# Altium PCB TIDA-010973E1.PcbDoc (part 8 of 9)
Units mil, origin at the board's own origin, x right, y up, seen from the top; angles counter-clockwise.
Board outline 5166 x 3669 mil, 8 copper layers (L01 - TOP, L02 - GND, L03 - SIG, L04 - GND, L05 - PWR, L06 - SIG, L07 - GND, L08 - BOTTOM), stack 61.7 mil thick; 677 components, 493 nets, 2522 pads, 1424 vias.
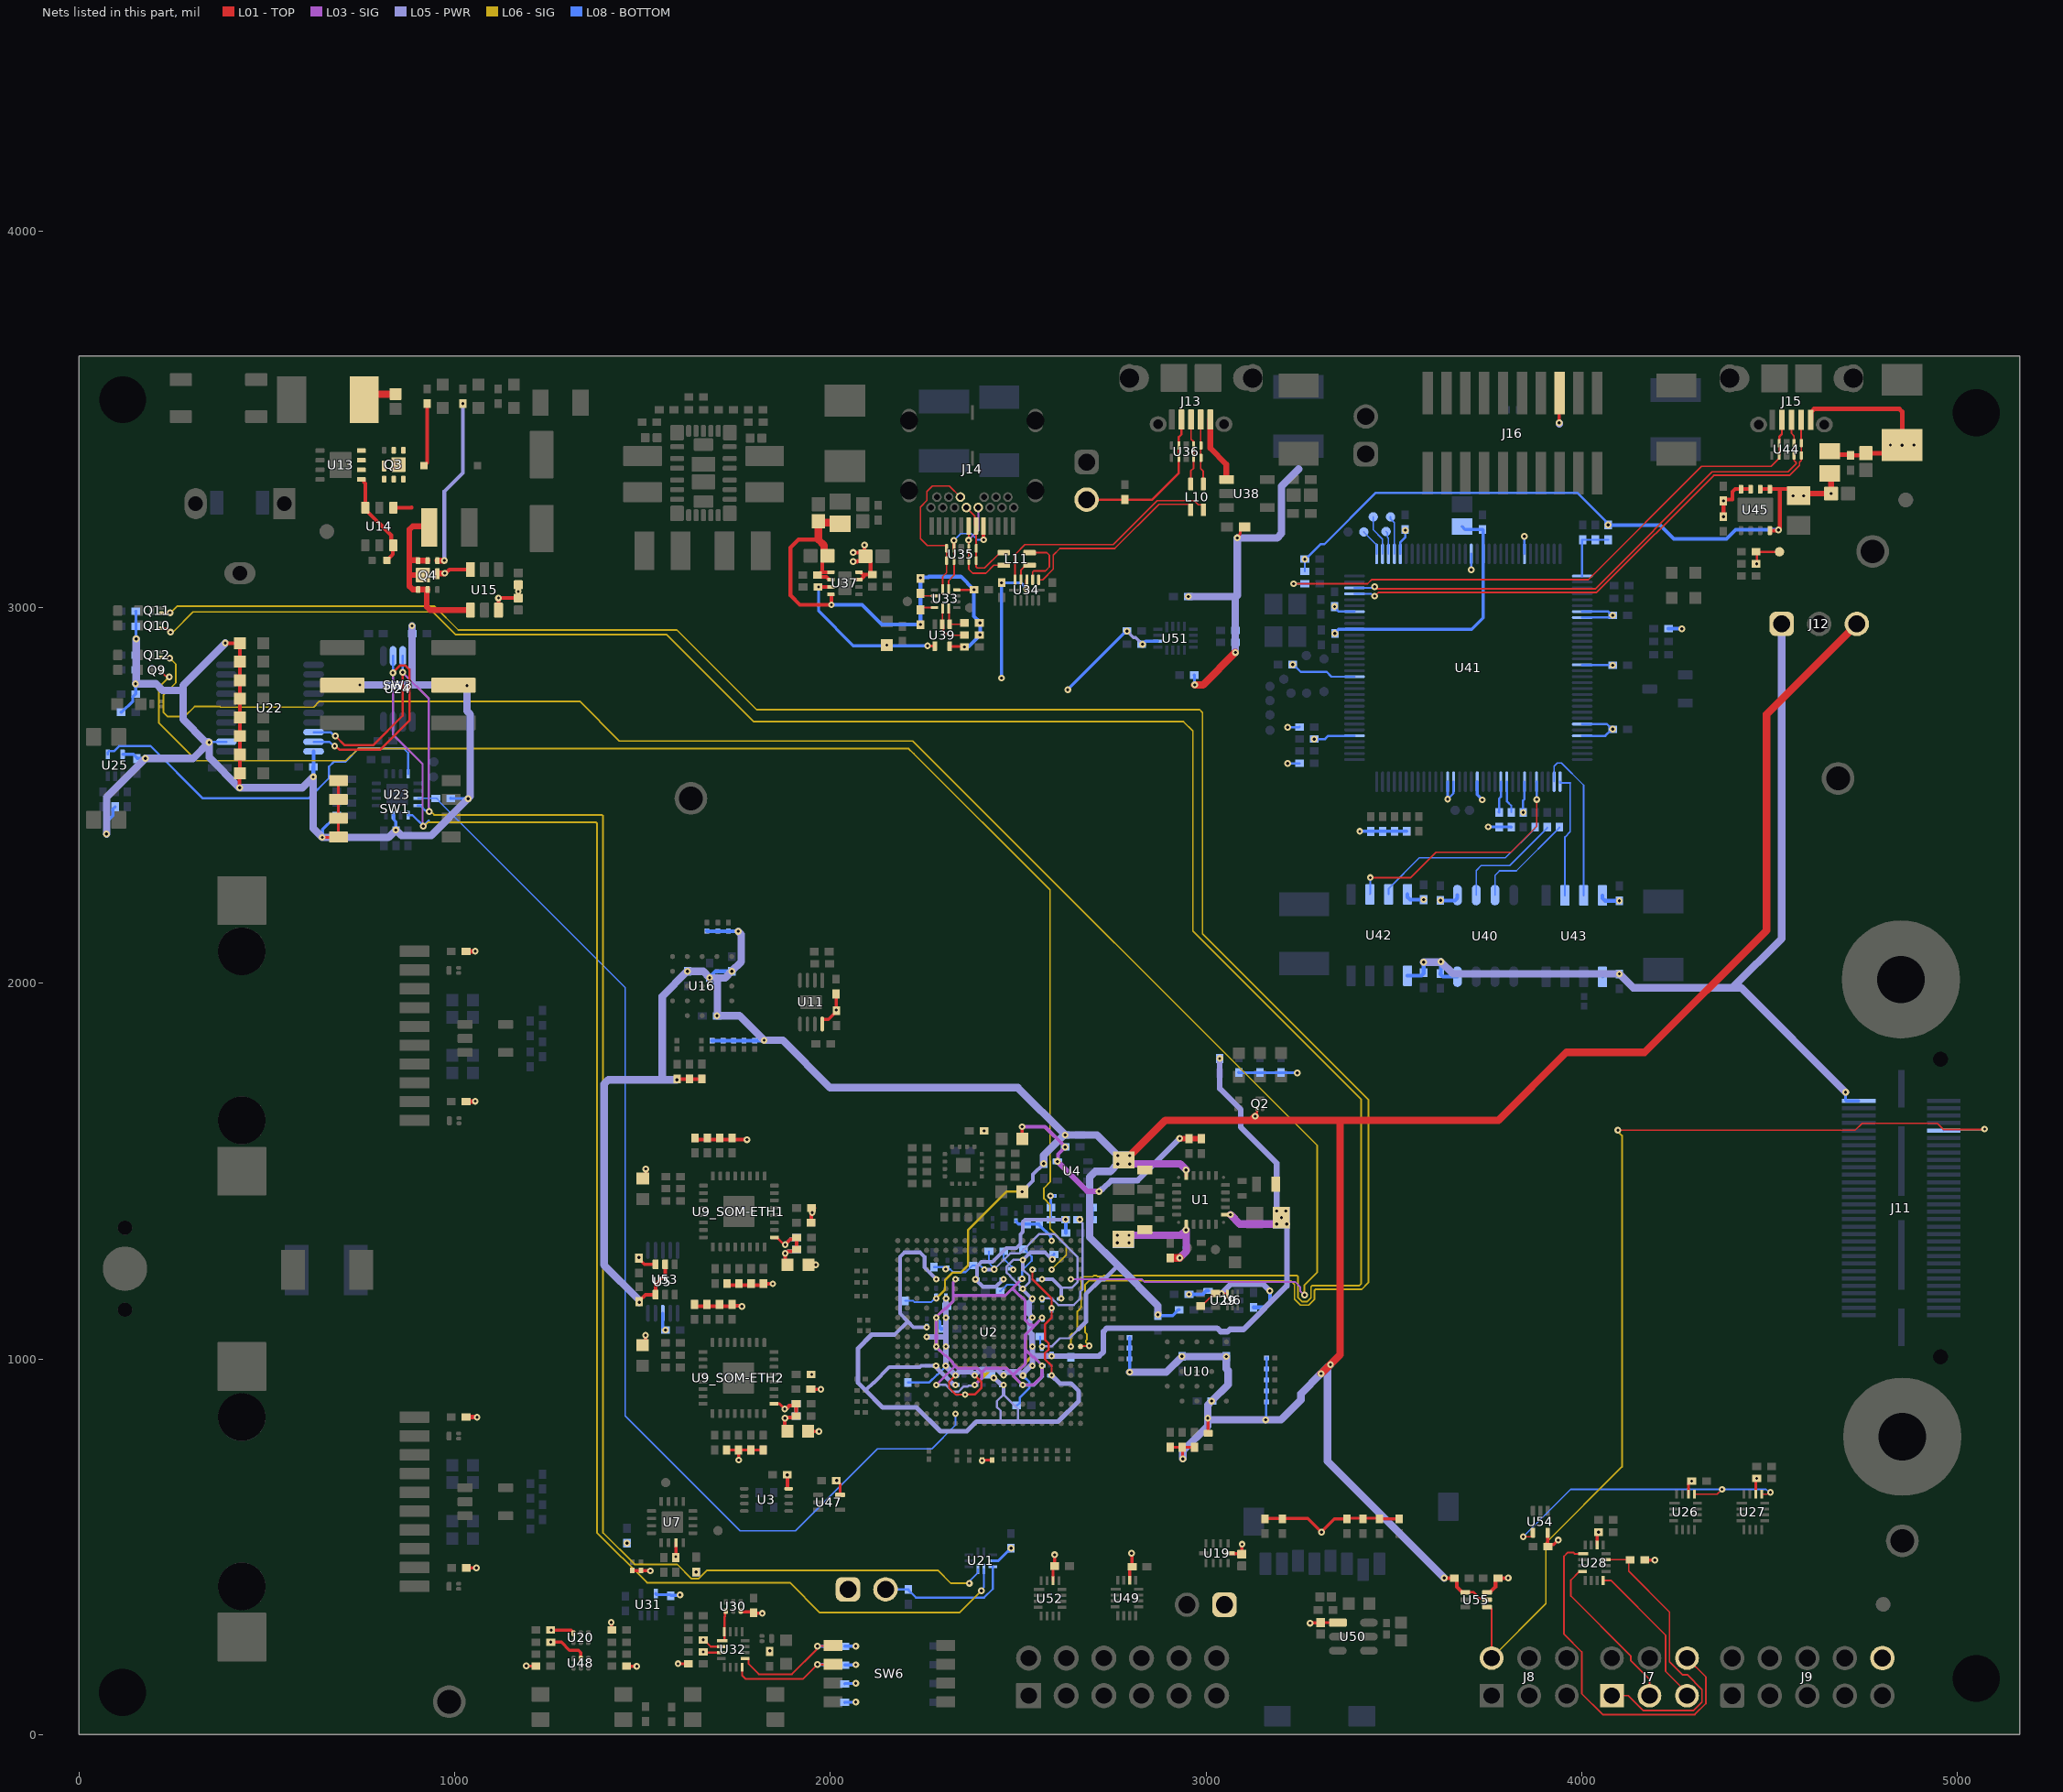
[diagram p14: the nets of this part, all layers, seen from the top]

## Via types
v1: diameter 18, hole 8, L01 - TOP to L08 - BOTTOM, tented both sides, 1389 vias
v2: diameter 19.68, hole 7.87, L01 - TOP to L08 - BOTTOM, 24 vias
v3: diameter 19.68, hole 7.87, L01 - TOP to L08 - BOTTOM, tented both sides, 11 vias

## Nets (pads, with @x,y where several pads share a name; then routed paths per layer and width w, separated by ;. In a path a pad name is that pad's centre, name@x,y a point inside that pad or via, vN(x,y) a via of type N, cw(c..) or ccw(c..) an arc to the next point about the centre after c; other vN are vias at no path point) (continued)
SOP2_SW: R125.1 SW6.6 U32.8 | length 317.1
  L01 - TOP w5: U32.8@1765.49,179.41 1765.49,157.51 1774,149 1928,149 v1(1966,187) 2006.79,187 SW6.6@2007.36,187.57
  L08 - BOTTOM w8: v1(1966,187) 1997.43,187 R125.1@1999.09,185.33
SOP3_SW: R124.1 SW6.5 U32.9 | length 328.6
  L01 - TOP w5: U32.9@1773.36,203.03 1781.24,203.03 1782.67,201.59 1782.67,188.26 1809.93,161 1898.01,161 1963.51,226.5 1963.51,233.51 v1(1966,236) 2005.79,236 SW6.5@2007.36,237.57
  L08 - BOTTOM w8: v1(1966,236) 1998.09,236 R124.1@1999.09,235
SOP_DRIVER_OEN: U30.4 U32.1 U32.16 | length 91.9
  L01 - TOP w6: U32.1@1712.34,250.28 1717.31,250.28 1718.24,251.21 U32.16@1718.24,273.9 1718.24,313.23 1719.86,314.85 U30.4@1719.86,324.85 ; U30.4@1718.24,323.23 U30.4@1719.86,324.85 ; U30.4@1722.18,327.17 U30.4@1719.86,324.85 ; U30.4@1722.18,329.65 1719.86,327.34 U30.4@1719.86,324.85
SOP_DRIVER_OEN_HPI: U26.13 U27.13 U54.4 | length 853.5
  L01 - TOP w4.3: U27.13@4478.62,640.24 4493.54,640.24 4498.29,645 v1(4502,645)
  L01 - TOP w4.5: v1@3844,528.48 v1(3844,527) 3866.37,527 3870.03,530.66 U54.4@3870.03,537.62 ; U26.13@4299.62,640.24 4360.24,640.24 v1(4373,653)
  L08 - BOTTOM w4.5: v1(3844,527) 3970,653 v1(4373,653) 4490.35,653 4498.35,645 v1(4502,645)
SPI2_CLK: J7.3 U28.4 | length 434.4
  L01 - TOP w4.5: U28.4@4001.5,434.38 3993.63,434.38 3970.75,411.5 3970.75,369.46 4130,210.21 4130,197.79 4180,147.79 J7.3@4180,104
SPI2_CS0: J7.1 R220.1 U28.11 | length 796.8
  L01 - TOP w4.5: U28.11@4064.5,465.87 4127.44,465.87 R220.1@4128.31,465 4125,461.68 4125,435 4233.5,326.5 4233.5,194.29 4267.9,159.89 4280.32,159.89 4319.75,120.46 4319.75,87.54 4296.46,64.25 4163.54,64.25 4123.79,104 J7.1@4080,104
SPI2_D0: J7.5 U28.8 | length 411.4
  L01 - TOP w4.5: U28.8@4056.62,410.76 4077.24,410.76 4223,265 4223,169 4280,112 J7.5@4280,104
SPI2_D1: J7.6 U28.1 | length 948.9
  L01 - TOP w4.5: U28.1@4003.47,481.62 3980.77,481.62 3977.15,485.25 3962.85,485.25 3952.75,475.15 3952.75,267.46 3999.75,220.46 3999.75,109.59 4055.59,53.75 4300.81,53.75 4330.25,83.19 4330.25,153.75 J7.6@4280,204
SYNC_OUT1_3V3: J8.2 J11.52 U55.4 | length 2799.8
  L01 - TOP w4.3: U55.4@3748.02,339.63 3755.31,339.63 3760,334.94 J8.2@3760,204 ; 4727.5,1608.75 4745.9,1627.15 4946.17,1627.15 4962.4,1610.92 5070.92,1610.92 v1(5072,1612)
  L01 - TOP w4.5: v1(4096,1609) 4096.25,1608.75 4727.5,1608.75
  L06 - SIG w4.5: J8.2@3760,204 3904.48,348.48 3904.48,510.48 4107,713 4107,1594.61 4096,1605.61 v1(4096,1609)
  L08 - BOTTOM w4.3: J11.52@4962.8,1608.17 4964.71,1610.09 5070.09,1610.09 v1(5072,1612)
TCK_XDS: R223.1 U40.3 | length 277.7
  L08 - BOTTOM w4.3: U40.3@3769,2234.5 3769,2287 3781,2299 3825.84,2299 3940,2413.16 R223.1@3940,2415.13
TDI_XDS: R225.1 U42.7 | length 474.4
  L08 - BOTTOM w4.3: U42.7@3486,2236.44 3486,2252.19 3567.47,2333.66 3796.5,2333.66 3876,2413.16 R225.1@3876,2415.13
TDO_XDS: U41.37 U42.6 | length 663.7
  L01 - TOP w4.3: v1(3437,2281) 3544.75,2281 3612.14,2348.39 3811.23,2348.39 3880,2417.16 v1(3880,2489)
  L08 - BOTTOM w4.3: U42.6@3436,2236.44 3437,2237.44 v1(3437,2281)
  L08 - BOTTOM w6: U41.37@3879.11,2536.15 3879.47,2535.79 3879.47,2489.53 v1(3880,2489)
TM4C129_TCK: TP10.1 U41.100 | length 102.8
  L08 - BOTTOM w4.3: TP10.1@3491,3241 3491,3235.4 3501.16,3225.24 U41.100@3501.16,3142.45
TM4C129_TDI: TP12.1 U41.98 | length 108.8
  L08 - BOTTOM w4.3: TP12.1@3445,3241 3445,3206.8 3469.66,3182.13 U41.98@3469.66,3142.45
TM4C129_TDO: TP13.1 U41.97 | length 72.6
  L08 - BOTTOM w4.3: TP13.1@3420,3201 3420,3200.49 3453.92,3166.58 U41.97@3453.92,3142.45
TM4C129_TMS: TP11.1 U41.99 | length 62.2
  L08 - BOTTOM w4.3: TP11.1@3479,3202 3482.96,3198.04 3482.96,3187.04 3485.41,3184.59 U41.99@3485.41,3142.45
TMS_XDS: R224.1 U40.2 | length 303.3
  L08 - BOTTOM w4.3: U40.2@3719,2234.5 3719,2300 3732,2313 3807.84,2313 3908,2413.16 R224.1@3908,2415.13
TPS_VSYS_5V0_ON: D19.2 R140.2 U37.3 U39.4 | length 446.8
  L01 - TOP w8: v1(2259,2898) 2259.57,2897.43 2277.75,2897.43 U39.4@2278.32,2896.87
  L01 - TOP w10: R140.2@1967.02,3054.28 v1(1968.99,3054.28) 1996.68,3054.28 1996.83,3054.44 U37.3@2001.6,3054.44
  L08 - BOTTOM w8: v1(1968.99,3054.28) 1968.99,2990.01 2061,2898 2150.28,2898 v1(2259,2898)
  other v1: 2150.28,2899.5
TUSB_OUT1: R137.1 U33.7 U39.2 | length 123.3
  L01 - TOP w4.3: U33.7@2299.13,2997.41 2298.56,2996.85 2298.56,2955.7 U39.2@2298,2955.13 2301.76,2951.38 2301.76,2936.24 2312,2926 2356.5,2926 R137.1@2357.31,2926.81
TUSB_OUT2: R136.1 U33.8 U39.1 | length 84.6
  L01 - TOP w4.3: U33.8@2314.87,2997.41 2316.28,2996 2316.28,2956.54 U39.1@2317.69,2955.13 2353.64,2955.13 R136.1@2357.31,2958.81
TUSB_OUT3: R135.1 U33.6 | length 39.8
  L01 - TOP w4.3: R135.1@2240,2993.69 2245.69,2999.38 U33.6@2277.47,2999.38
TUSB_VBUS_DET: R138.1 U33.4 | length 38.9
  L01 - TOP w4.3: R138.1@2240,3034.31 2243.44,3030.87 U33.4@2277.47,3030.87
UART0_RXD_XDS: U41.34 U43.7 | length 441.7
  L08 - BOTTOM w4.3: U41.34@3926.36,2536.15 3926.36,2577.84 3934.52,2586 3946,2586 4005,2527 U43.7@4005,2233.44
UART0_TXD_XDS: U41.33 U43.6 | length 334.9
  L08 - BOTTOM w4.5: U43.6@3955,2233.44 3955,2388.88 3969,2402.88 3969,2533
  L08 - BOTTOM w6: U41.33@3942.1,2536.15 3942.1,2533.87 3942.97,2533 3969,2533
UI_I2C_SCL: U21.2 U22.18 U23.12 U24.7 | length 4351.1
  L01 - TOP w6: v1(683,2658) 708,2633 783,2633 862,2712 v1(862,2827)
  L03 - SIG w6: v1(862,2827) 931,2758 931,2459 v1(933,2457)
  L06 - SIG w4.5: v1(933,2457) 936.65,2457 945.6,2448.05 1392.67,2448.05 1395.31,2445.42 1395.31,537.29 1479.35,453.25 1592.46,453.25 1630.65,415.07 1649.15,415.07 1671.08,437 2287,437 2321,403 v1(2370,403)
  L08 - BOTTOM w4.5: v1(2370,403) 2372.58,405.58 2372.58,410.96 2393.13,431.5 U21.2@2393.13,441.35
  L08 - BOTTOM w6: U22.18@625.08,2668.06 669.69,2668.06 679.75,2658 v1(683,2658) ; v1(862,2827) 862.06,2827.06 862.06,2870.54 U24.7@862.11,2870.6 ; U23.12@902.24,2472.63 909.32,2472.63 922.66,2459.3 930.7,2459.3 v1(933,2457)
UI_I2C_SDA: U21.1 U22.19 U23.13 U24.6 | length 4599.1
  L01 - TOP w6: v1(681,2631) 684.25,2631 694.25,2621 801.94,2621 880,2699.06 880,2834.46 869.46,2845 854.54,2845 836,2826.46 v1(836,2826)
  L03 - SIG w6: v1(836,2826) 836,2662.5 915,2583.5 915,2420 v1(917,2418)
  L06 - SIG w4.5: v1(917,2418) 919.27,2418 929.27,2428 1376.36,2428 1379,2425.36 1379,538 1512.43,404.57 1892.44,404.57 1972,325 2344,325 v1(2402,383)
  L08 - BOTTOM w4.5: v1(2402,383) 2402,386.25 2408.87,393.12 U21.1@2408.87,441.35
  L08 - BOTTOM w6: U22.19@625.08,2642.47 667.01,2642.47 678.48,2631 v1(681,2631) ; v1(836,2826) 836.26,2826.26 836.26,2870.34 U24.6@836.52,2870.6 ; U23.13@876.65,2447.04 887.96,2447.04 v1(917,2418) 932,2433
UI_I2C_SELECT: J5.2 R93.2 U21.10 | length 364.5
  L08 - BOTTOM w6: J5.2@2147,387 2207.69,387 R93.2@2208,386.69 2208,384.72 2227.72,365 2409.46,365 2432.5,388.04 U21.10@2432.5,447.25
UI_LED1_G: Q12.1 U2.T2 | length 4827.5
  L01 - TOP w4.5: Q12.1@220.01,2866.8 220.91,2865.9 241.1,2865.9 v1(242,2865)
  L03 - SIG w4.5: v1(2640.27,1212.36) 2729.83,1212.36 2828.64,1212.36 2836,1205 3237.3,1205 3250.36,1191.94 3250.36,1181.64 v1(3262,1170)
  L06 - SIG w4.5: v1(242,2865) 258.25,2848.75 258.25,2799.75 225.75,2767.25 225.75,2719.85 235.86,2709.75 281.75,2709.75 308.25,2736.25 375.74,2736.25 377.35,2734.64 625.13,2734.64 640.49,2750 1333,2750 1438.5,2644.5 2219.5,2644.5 3296,1568 3296,1231 3262,1197 v1(3262,1170)
UI_LED1_R: Q9.1 U2.U4 | length 3799.9
  L01 - TOP w4.5: Q9.1@220.01,2826.8 221.98,2826.8 231.19,2817.58 238.42,2817.58 v1(241,2815)
  L06 - SIG w4.5: v1(241,2815) 213,2787 213,2693 313.99,2592.01 711.25,2592.01 743.49,2624.25 2208.75,2624.25 2222,2611 2585,2248 2585,1527.08 2585.25,1526.83 2585.25,1471.2 2568.75,1454.7 2568.75,1426.85 2585,1410.6 2585,1346.37 2627.69,1303.68 2627.69,1276.56 v1(2589.09,1237.95)
UI_LED2_G: Q11.1 U2.J1 | length 5635.6
  L01 - TOP w4.5: U2.J1@2665.86,1033.23 2666.74,1034.11 2688.11,1034.11 v1(2689,1035)
  L01 - TOP w6: Q11.1@220.01,2984.8 241.8,2984.8 v1(243,2986)
  L06 - SIG w4.5: v1(243,2986) 244.46,2986 261.46,3003 947,3003 1010,2940 1592,2940 1804,2728 1830,2728 2983,2728 2990.5,2720.5 2990.5,2131.5 3432,1690 3432,1203.26 3414.13,1185.39 3291.29,1185.39 3288.65,1182.75 3288.65,1158.96 3273.04,1143.35 3250.96,1143.35 3235.35,1158.96 3235.35,1197.99 3225.19,1208.15 2688.42,1208.15 2678.26,1197.99 2678.26,1070.67 2683.01,1065.92 2683.01,1051.71 2679.73,1048.43 2679.73,1044.27 v1(2689,1035)
UI_LED2_R: Q10.1 U2.J2 | length 5604.1
  L01 - TOP w6: Q10.1@220.01,2944.8 232.75,2944.8 243.54,2934 v1(244,2934)
  L06 - SIG w4.5: v1(244,2934) 246.3,2936.3 252.44,2936.3 304.15,2988 942,2988 1002,2928 1564,2928 1796,2696 2940,2696 2965,2671 2965,2139 3413,1691 3413,1200.64 3407.25,1194.89 3281.79,1194.89 3279.15,1192.25 3279.15,1162.9 3269.1,1152.85 3254.9,1152.85 3244.85,1162.9 3244.85,1219.36 3242.21,1222 2727.25,1222 2725.1,1219.85 2710.9,1219.85 2708.75,1222 2701.25,1222 2698.1,1218.85 2670.49,1218.85 2667.86,1216.21 2667.86,1137.08 2657.42,1126.64 2657.42,1077.31 2647.37,1067.26 2642.9,1067.26 2640.27,1064.62 v1(2640.27,1033.23)
USB-AB_C_DM: J13.2 L10.1 U36.5 U36.6 | length 174.6
  L01 - TOP w4.5: J13.2@2985.59,3500.07 2985.59,3369.41 2992.73,3362.27 L10.1@2992.73,3328.45
USB-AB_C_DP: J13.3 L10.4 U36.4 U36.7 | length 177.7
  L01 - TOP w4.5: L10.4@2959.27,3328.45 2959.27,3363.07 2967,3370.8 U36.4@2967,3398.13 U36.7@2967,3431 2967,3440.83 2960,3447.83 J13.3@2960,3500.07
USB-AB_ID: J13.4 J20.2 R132.2 U36.2 U36.9 | length 420.1
  L01 - TOP w6: J20.2@2682,3287 2857,3287 2927.63,3357.63 U36.2@2927.63,3398.13 U36.9@2927.63,3431 2927.63,3453.58 2934.41,3460.36 J13.4@2934.41,3500.07
USB-C_D_M: J14.A7 J14.B7 L11.4 U35.2 U35.9 | length 319
  L01 - TOP w4.3: J14.A7@2368.16,3216.64 2368.42,3216.37 2368.42,3157.7 U35.2@2368.69,3157.44 U35.9@2368.69,3124.56 2368.69,3101.31 2379,3091 2414.1,3091 2435.37,3112.27 L11.4@2461.55,3112.27
  L03 - SIG w4.5: v1(2368,3179) 2393.75,3204.75 J14.B7@2393.75,3265.85
USB-C_D_P: J14.A6 J14.B6 L11.1 U35.1 U35.10 | length 260.2
  L01 - TOP w4.3: J14.B6@2362.25,3265.85 2384.09,3244.02 2384.09,3220.39 J14.A6@2387.84,3216.64 2388.11,3216.37 2388.11,3157.7 U35.1@2388.37,3157.44 U35.10@2388.37,3124.56 2388.37,3107.52 2390.89,3105 2410.98,3105 2451.71,3145.73 L11.1@2461.55,3145.73
USBMICROAB_C_DM: L10.2 U34.5 | length 643.6
  L01 - TOP w4.3: U34.5@2491.5,3073.56 2491.5,3140.77 2517.74,3167 2752.77,3167 2870.2,3284.43 2968.36,3284.43 2979.39,3273.4 2987.99,3273.4 2992.73,3268.66 L10.2@2992.73,3259.55
USBMICROAB_C_DP: L10.3 U34.1 | length 521.3
  L01 - TOP w4.3: U34.1@2554.5,3073.56 2564.88,3073.56 2593.3,3101.98 2593.3,3139 2611,3156.7 2757.03,3156.7 2874.47,3274.13 2954.53,3274.13 2959.27,3269.39 L10.3@2959.27,3259.55
USBTYPEC_C_DM: L11.3 U34.4 | length 54.1
  L01 - TOP w4.3: U34.4@2507.25,3073.56 2507.25,3098.91 2520.61,3112.27 L11.3@2530.45,3112.27
USBTYPEC_C_DP: L11.2 U34.2 | length 157.2
  L01 - TOP w4.3: L11.2@2530.45,3145.73 2576.27,3145.73 2583,3139 2583,3108 2572.23,3097.23 2541.27,3097.23 2538.75,3094.71 U34.2@2538.75,3073.56
USBTYPEC_CC1: J14.A5 U33.1 U35.4 U35.7 | length 265.6
  L01 - TOP w4.3: U33.1@2314.87,3048.59 2314.87,3070.87 2329.32,3085.31 U35.7@2329.32,3124.56 U35.4@2329.32,3157.44
  L01 - TOP w8: v1(2329,3178) 2329.16,3177.84 2329.16,3157.59 U35.4@2329.32,3157.44
  L01 - TOP w10: J14.A5@2407.53,3216.64 2407.76,3216.4 2407.76,3180.24 v1(2408,3180)
  L08 - BOTTOM w4.3: v1(2329,3178) 2347.15,3196.15 2375.1,3196.15 2391.25,3180 v1(2408,3180)
USBTYPEC_CC2: J14.B5 U33.2 U35.5 U35.6 | length 436.6
  L01 - TOP w4.3: U33.2@2299.13,3048.59 2299.13,3081.79 2309.63,3092.29 U35.6@2309.63,3124.56 U35.5@2309.63,3157.44 2309.63,3162.65 2307.69,3164.59 2260.19,3164.59 2258.41,3164.59 2248.1,3174.69 2240,3182.79 2240,3267.57 2257.22,3284.78 2257.22,3308.22 2272,3323 2316.91,3323 J14.B5@2346.5,3293.41
USER_INT: R105.2 U2.B14 U23.11 | length 3053.5
  L08 - BOTTOM w4.3: U23.11@902.24,2492.31 950,2492.31 R105.2@950.31,2492 952.28,2492 959.98,2484.31 959.98,2482.34 1454,1988.32 1454,849 1760.15,542.85 1906.96,542.85 2125.06,760.95 2270.06,760.95 2333.18,824.07 v1(2333.18,854.09)
USER_PB: U23.8 U25.4 | length 1002.9
  L08 - BOTTOM w6: U25.4@77.32,2609.13 77.32,2614.47 80.22,2617.37 94.24,2617.37 108.19,2631.32 190.68,2631.32 330,2492 612,2492 665.82,2545.82 665.82,2576.27 679.54,2590 710,2590 745,2625 864.46,2625 876.65,2612.81 U23.8@876.65,2557.28
V_IN: C96.1 L6.1 Q3.1 Q3.2 Q3.5 Q3.6 Q3.8 Q4.1 Q4.2 Q4.5 Q4.6 Q4.8 R64.2 U14.4 U15.4 | length 729.8
  L01 - TOP w10: U14.4@837.4,3265.51 885.51,3265.51 886,3266 ; L6.1@919.13,3377 927,3384.87 R64.2@927,3542.31
  L01 - TOP w15: 882,3086 Q4.8@916,3086 ; Q4.2@928.8,3047.61 Q4.2@928.56,3047.61 ; Q4.5@928.8,3124.39 Q4.6@903.2,3124.39 901.85,3125.74 882.67,3125.74 880,3128.41 ; C96.1@932.85,3213 929.85,3216 888.79,3216 880,3207.21 880,3128.41 ; U15.4@1042.28,2992.87 934.79,2992.87 926,3001.65 926,3044.82 927.2,3046.02 927.2,3046.26 Q4.2@928.56,3047.61 ; 880,3128.41 880,3056.4 888.79,3047.61 Q4.1@903.2,3047.61 Q4.2@928.56,3047.61
V_PLUG: C97.1 C98.1 F1.1 Q3.4 Q3.7 U13.1 U13.2 U13.3 U13.4 U14.3 U14.6 | length 351
  L01 - TOP w10: U13.1@752.12,3340.61 757.83,3340.61 758.93,3339.51 758.93,3333.8 762.6,3330.13 U14.6@762.6,3265.51 762.6,3260.59 768.43,3254.76 769.15,3254.76 831.57,3192.34 831.57,3170.94 U14.3@837.4,3165.12 836.17,3163.89 836.17,3141.49 C98.1@820,3125.31
  L01 - TOP w20: F1.1@759.65,3553 774.35,3567.69 C97.1@843,3567.69
VBUS_MICRO_AB_5V0: J13.1 U38.1 | length 177.8
  L01 - TOP w15: J13.1@3011.18,3500.07 3011.18,3423.82 3054,3381 3054,3341.27 U38.1@3054.87,3340.4
VBUS_XDS: C143.1 C144.2 D22.2 J15.1 L12.2 | length 567.2
  L01 - TOP w12: J15.1@4609.18,3499.07 4611.06,3500.94 4611.06,3520.97 4618.08,3528 4845.4,3528 4852.43,3520.97 v1(4852.43,3431.76) 4831.34,3410.67 C144.2@4756,3410.67 4750.02,3404.69 C143.1@4715,3404.69 4713.03,3406.65 4668.87,3406.65 L12.2@4660,3415.53
  other v1: 4821,3432 4884,3432
VBUS_XDS_5V: C139.2 C142.2 C166.1 L12.1 R146.2 R147.2 U45.1 U45.2 U45.8 | length 1819.3
  L01 - TOP w10: U45.2@4474.8,3314.76 U45.1@4500.39,3314.76 4523.02,3314.76 ; U45.8@4500.39,3204.52 4521.14,3204.52 v1(4523.02,3206.4) 4527,3210.38 4527,3310.78 4523.02,3314.76 ; v1(4562,3297) 4563,3298 C166.1@4577,3298 4560.24,3314.76 4523.02,3314.76 ; v1(4590,3297) C166.1@4596,3303 ; L12.1@4660,3356.47 L12.1@4663.33,3353.14
  L01 - TOP w15: C166.1@4596,3303 v1(4663.33,3303) L12.1@4663.33,3353.14
  L08 - BOTTOM w4.3: R146.2@3262.98,3095.85 v1(3262.98,3128.35)
  L08 - BOTTOM w6: v1(3262.98,3128.35) 3264.95,3128.35 3304.75,3168.15 3314.74,3168.15 3451.78,3305.18 3988.27,3305.18 4063.16,3230.3 4063.16,3226.21 v1(4070,3219.37)
  L08 - BOTTOM w10: v1(4070,3219.37) 4208.13,3219.37 4245.19,3182.31 4385.28,3182.31 4409.37,3206.4 v1(4523.02,3206.4)
VCORE_1V25: C1.2 C2.2 C3.2 C4.2 C5.2 C6.2 C7.2 C8.2 C9.2 C10.2 C11.2 C12.2 C13.2 C14.1 C15.1 C16.1 C20.1 C21.1 C40.2 C41.2 C49.1 C50.1 C53.2 L1.2 R11.2 U1.8 U2.D13 U2.F7 U2.F9 U2.F12 U2.F14 U2.G6 U2.G15 U2.H4 U2.J6 U2.J15 U2.K17 U2.M6 U2.M15 U2.P6 U2.P15 U2.R7 U2.V7 | length 3115.9
  L01 - TOP w5: v1(2333.18,956.46) 2315.78,939.06 2315.78,923.66 2334.16,905.28 v1(2358.77,905.28)
  L01 - TOP w6: v1(2358.77,905.28) 2384.09,905.28 2402.26,923.45 2402.26,938.56 v1(2384.36,956.46)
  L01 - TOP w10: U1.8@3057.65,1384 v1(3065,1384)
  L03 - SIG w20: v1(3065,1384) 3090,1359 v1(3188,1359)
  L05 - PWR w6: 2512.31,1238.23 2530.21,1220.33 2530.21,1204.67 v1(2512.31,1186.77) 2511.93,1186.77 2479.03,1219.67 2479.03,1220.33 2468.82,1230.54 2468.82,1245.37 2487,1263.54 v1(2512.31,1263.54)
  L05 - PWR w10: v1(2512.31,1186.77) 2513.85,1185.24 2513.85,1182.69 2536.35,1160.18 v1(2537.91,1160.18) ; 2512.31,1238.23 v1(2512.31,1263.54) 2532.21,1283.44 2572.17,1283.44 v1(2590.6,1265.01)
  L05 - PWR w15: v1(2256.41,1058.82) 2306.77,1058.82 2307.59,1058 ; v1@2307.33,982.11 2307.33,1032.96 v1(2307.59,1033.23) 2307.59,1058 ; v1@2307.43,981.84 2332.81,956.46 v1(2333.18,956.46) 2333.99,956.46 2343.94,966.4 2373.61,966.4 2383.55,956.46 v1(2384.36,956.46) 2399.99,972.08 2423.67,972.08 2423.99,972.4 2445.19,972.4 v1(2461.13,956.46) 2461.95,956.46 2470.89,965.4 2502.41,965.4 2511.67,956.13 v1(2512.49,956.13) ; v1(2308,1161) 2307.8,1160.8 2307.8,1110.2 v1(2307.59,1110) 2307.59,1058 ; 2516.6,965.28 2532.8,981.47 2537.33,981.47 v1(2537.91,982.05) 2537.91,1008 ; 2530.6,1101.88 2530.6,1071.61 2537.49,1064.73 2537.49,1033.65 v1(2537.91,1033.23) 2537.91,1008 ; v1(2537.91,1110) 2537.91,1110.81 2528.6,1120.12 2528.6,1150.06 2537.91,1159.37 v1(2537.91,1160.18) ; v1(3036.5,1799.69) 3036.5,1719.82 3092,1664.32 3092,1617.09 3188,1521.09 v1(3188,1394) ; v1(3215,1359) 3215,1194.18 3099.82,1079 3063.68,1079 3057.28,1072.6 3038.72,1072.6 3029.32,1082 2736,1082 2726.95,1072.95 2726.95,1019.28 2715.51,1007.84 2589.29,1007.84 v1(2589.09,1007.64) 2588.72,1008 2537.91,1008
  L08 - BOTTOM w6: C50.1@2207,937.68 2263.5,937.68 2284.08,958.26 2285.43,958.26 2307.06,979.88 v1(2307.06,981.84) ; v1(2308,1161) 2308,1142 C15.1@2310,1140 ; C14.1@2495.76,876.55 2497.73,876.55 2504.57,883.4 2504.57,897.81 2530.21,923.45 2530.21,938.28 2519.73,948.77 2518.06,948.77 2512.49,954.34 v1(2512.49,956.13) ; C40.2@2589,1015.34 2588.59,1015.74 2588.59,1016.11 2589.04,1015.66 2589.04,1007.68 v1(2589.09,1007.64) 2636.98,1007.64 C49.1@2640.37,1004.25 ; v1(2590.6,1265.01) C16.1@2590.6,1272.9 ; C16.1@2595.28,1277.57 C16.1@2590.6,1272.9 ; C16.1@2595.97,1279.32 2590.6,1273.96 C16.1@2590.6,1272.9
  other v1: 3200.57,1375.95 3212,1394
VDD_XDS3V3: C148.1 C149.1 C150.1 C153.1 C154.1 C155.1 C156.1 C157.1 C158.1 C161.1 C162.1 C163.1 C167.1 C168.1 R151.1 R152.1 R154.1 R155.1 R156.1 R157.1 R163.1 R164.1 R165.2 R166.2 TP27.1 U40.1 U41.7 U41.8 U41.16 U41.26 U41.28 U41.39 U41.47 U41.51 U41.52 U41.69 U41.79 U41.90 U41.101 U41.113 U41.122 U42.8 U43.8 U45.3 U45.4 | length 1846.7
  L01 - TOP w6: v1(4465.65,3116) 4465.65,3146.03 C161.1@4463.69,3148 TP27.1@4526,3148
  L01 - TOP w10: v1(4377,3241.69) v1(4377,3283.31) 4380.54,3286.86 4401,3286.86 4401,3308 4407.76,3314.76 U45.4@4423.61,3314.76 ; U45.4@4424.31,3314.76 U45.3@4449.2,3314.76
  L08 - BOTTOM w6: v1@3218,2585 R163.1@3248.63,2585 ; v1@3219,2681 3247.92,2681 R164.1@3248.62,2681.7 ; v1(3230.68,2848) 3232.65,2848 3252.24,2828.42 3321.12,2828.42 3333.86,2815.68 U41.79@3394.86,2815.68 ; v1(3287.99,2649.7) 3316.7,2649.7 3325.2,2658.2 U41.69@3394.86,2658.2 ; v1(3342,3002.31) 3342,3000.35 3353.44,2988.91 U41.90@3394.86,2988.91 ; U41.101@3516.91,3142.45 3517.27,3142.81 3517.27,3173.77 3530,3186.5 C153.1@3530,3207.31 ; v1(3643,2490) 3658.28,2505.28 3658.28,2535.79 U41.51@3658.64,2536.15 ; U41.113@3705.88,3142.45 U41.113@3705.88,3142.45 3705.94,3100.06 v1(3706,3100) ; v1(3844,2454.68) 3844,2486 3847.62,2489.62 U41.39@3847.62,2536.15 ; v1(3847,3189) 3847.31,3188.69 3847.31,3142.76 U41.122@3847.62,3142.45 ; U41.28@4001.16,2658.2 4062.54,2658.2 C157.1@4080.35,2676 ; U41.26@4001.16,2689.69 4066.65,2689.69 C157.1@4080.35,2676 ; U41.16@4001.16,2847.17 4081.14,2847.17 v1(4082.31,2846) ; U41.8@4001.16,2973.16 4076.47,2973.16 v1(4082.31,2979) 4080.35,2979 4070.44,2988.91 U41.7@4001.16,2988.91 ; v1(4082.31,2676) C157.1@4080.35,2676
  L08 - BOTTOM w8: v1(3409,2404) 3409.16,2404.16 3533.84,2404.16 R157.1@3534,2404.32 ; U41.52@3642.89,2536.15 3642.96,2536.09 3642.96,2511.04 3643,2511 v1(3643,2490) ; U41.47@3721.63,2536.15 3721.63,2501.37 v1(3735,2488) ; v1(3751,2416) 3811.31,2416 R151.1@3812,2415.32
  L08 - BOTTOM w10: U42.8@3536,2236.44 3536,2229.13 3542.81,2222.32 v1(3579,2222.32) ; v1(3624,2220.32) 3662.71,2220.32 3669,2226.61 U40.1@3669,2234.5 ; U43.8@4055,2233.44 4055,2226.13 4061.81,2219.32 v1(4100,2219.32) ; R165.2@4230.69,2943.55 4230.9,2943.33 4266.1,2943.33 v1(4266.31,2943.11)
  other v1: 3217,2585 3217,2681 3530,3205.35
VDDA18_AM261_OSC_PL: C48.2 L13.2 U2.U8 | length 60.5
  L08 - BOTTOM w5: L13.2@2461.69,1287 2461.69,1266.63 2482.39,1245.93 2484.26,1245.93 2486.72,1243.46 v1(2486.72,1237.95)
VDDA_AM261_1V8_LDO: C42.2 C45.2 C51.1 C60.2 C209.1 C216.1 C217.2 L13.1 U2.P3 U2.T5 U2.U10 U2.U11 U2.U15 | length 741.5
  L05 - PWR w6: v1(2436.24,1238.38) 2478.79,1280.92 2504.38,1280.92 2556.08,1332.62 2596.5,1332.62 2658.17,1270.96 2658.17,1204.95 2642.54,1189.32 2614.68,1189.32
  L05 - PWR w10: v1(2409.95,1237.95) 2410.17,1238.17 2436.03,1238.17 v1(2436.24,1238.38) ; v1(2563.5,1212.36) 2591.64,1212.36 2614.68,1189.32 v1(2614.68,1161.18)
  L08 - BOTTOM w5: C216.1@2276.15,1244.48 2304.33,1244.48 2307,1241.81 v1(2307,1238.98) 2307.46,1238.52 2319.67,1238.52 2327.11,1231.08 2360.47,1231.08 2377.87,1248.48 C51.1@2379.83,1248.48 2399.15,1248.48 2401.16,1246.46 ; 2403.18,1244.45 2401.16,1246.46 ; v1(2409.95,1237.95) 2409.95,1241.82 2407.33,1244.45 2403.46,1244.45 2401.44,1246.46 2401.16,1246.46 ; L13.1@2422.32,1287 2422.32,1255.03 C45.2@2431.61,1245.74 ; C209.1@2555,1211 C209.1@2556.36,1212.36 ; v1(2563.5,1212.36) C209.1@2556.36,1212.36 ; v1@2567.99,1212.88 2556.88,1212.88 C209.1@2556.36,1212.36
VDDA_AM261_3V3: C55.2 C58.1 C210.2 L14.2 U2.T9 U2.T12 | length 482.9
  L05 - PWR w10: v1(2461.13,1212.36) 2440.87,1192.1 2405.9,1192.1 v1(2386,1212) 2386,1214.16 2390.05,1218.22 2390.05,1246.2 2402.14,1258.28 2432.28,1258.28 2468.82,1294.82 2494.97,1294.82 2506.62,1306.48 2506.62,1322.97 2505.94,1323.65 2505.94,1331.94 2512.31,1338.31 2512.31,1365.14 2518.17,1371 v1(2626.37,1371)
  L08 - BOTTOM w10: v1(2626.37,1371) 2626.7,1370.67 2626.7,1335.99 C58.1@2627.03,1335.66
VDDA_AM261_3V3_USB: C190.2 L15.2 U2.P5 | length 335
  L05 - PWR w6: v1(2563.5,1161.18) 2589.36,1161.18 2607.26,1143.28 2647.68,1143.28 2665.2,1160.8 2665.2,1178.83 2671.2,1184.83 2671.2,1361.49 2665.8,1366.89 2664.22,1368.46 v1(2664.22,1371)
  L05 - PWR w10: v1@2563.5,1158.18 v1(2563.5,1161.18)
VDDC_1V2: C169.1 C170.1 C171.1 U41.87 U41.115 | length 706.7
  L08 - BOTTOM w8: v1(3343,2930.69) 3343,2932.65 3352.01,2941.66 U41.87@3394.86,2941.66 3706.66,2941.66 3737.38,2972.38 U41.115@3737.38,3142.45 3737.32,3142.51 3737.32,3206 C170.1@3736,3207.31 3689.16,3207.31 C169.1@3681,3215.47
VDDIO_SOM-ETH1: C69_SOM-ETH1.1 C70_SOM-ETH1.1 C71_SOM-ETH1.1 C72_SOM-ETH1.1 L4_SOM-ETH1.1 U9_SOM-ETH1.17 | length 282.7
  L01 - TOP w7: U9_SOM-ETH1.17@1851.13,1323.58 1852.56,1322.16 1859.44,1322.16 1875.21,1306.4 1879.51,1306.4 v1@1880,1306.88
  L01 - TOP w10: v1(1880,1304) 1880,1306.88 1881.89,1306.88 1893.64,1318.63 1905.61,1318.63 C69_SOM-ETH1.1@1910.45,1323.47 1910.45,1318.63 C70_SOM-ETH1.1@1910.45,1290.99 1905.61,1286.15 1887.31,1286.15 1882.16,1281 v1(1880,1281) 1880,1257.21 L4_SOM-ETH1.1@1886.57,1250.64
  L08 - BOTTOM w10: v1(1880,1281) 1882.16,1281 1887.31,1286.15 1905.61,1286.15 C71_SOM-ETH1.1@1910.45,1290.99 1910.45,1318.63 C72_SOM-ETH1.1@1910.45,1323.47 1905.61,1318.63 1893.64,1318.63 1880,1304.99 v1(1880,1304)
VDDIO_SOM-ETH2: C69_SOM-ETH2.1 C70_SOM-ETH2.1 C71_SOM-ETH2.1 C72_SOM-ETH2.1 L4_SOM-ETH2.1 U9_SOM-ETH2.17 | length 271.9
  L01 - TOP w7: U9_SOM-ETH2.17@1850.13,880.58 1850.26,880.46 1864.96,880.46 v1(1878.78,866.64) v1@1879.13,866.64
  L01 - TOP w10: v1@1879.13,866.64 1881.75,866.64 1890.75,875.63 1904.61,875.63 C69_SOM-ETH2.1@1909.45,880.47 C70_SOM-ETH2.1@1909.45,847.99 1907.48,847.99 1903.98,844.49 1880.99,844.49 v1(1879.13,842.64) 1879.13,814.08 L4_SOM-ETH2.1@1885.57,807.64
  L08 - BOTTOM w10: v1(1879.13,842.64) 1880.99,844.49 1905.95,844.49 C71_SOM-ETH2.1@1909.45,847.99 C72_SOM-ETH2.1@1909.45,880.47 1904.61,875.63 1890.75,875.63 v1@1881.75,866.64
VDDS_AM261_LDO_1V8: C198.2 C199.2 C200.2 C201.2 C202.2 C203.2 C204.2 C205.2 C206.1 U2.E9 U2.E14 U2.F4 U2.G16 U2.L17 U2.N4 U2.T16 U2.U6 | length 2481.3
  L01 - TOP w6: v1(2537.91,1237.95) 2537.91,1212.36 2589.09,1161.18 v1(2589.09,1135.59) 2589.09,1109.72 2571.19,1091.82 2571.19,1051.4 2581.4,1041.2 2581.4,1025.81 2571.19,1015.6 2571.19,999.67 2589.09,981.77 v1(2589.09,956.46)
  L05 - PWR w6: 2452.59,833.19 2453.44,834.04 2453.44,862.06 2443.23,872.27 2443.23,887.65 2461.13,905.55 ; 2461.13,905 2499.74,866.4 2499.74,833.19
  L05 - PWR w10: 2074.5,935.94 2074.5,1027.64 2110.76,1063.9 2170.62,1063.9 2171.62,1064.9 2206.29,1099.57 ; 2092.16,918.28 2096.14,918.28 2114.76,936.9 2116.04,936.9 2157.04,977.9 2238.04,977.9 2242.04,981.9 v1(2281.31,981.9) ; v1(2256.41,1084.41) 2221.45,1084.41 2206.29,1099.57 ; v1(2282,1212.36) 2250.9,1243.46 2250.9,1271.6 2239.06,1283.44 2196.99,1283.44 2185.33,1271.79 2185.33,1120.53 2206.29,1099.57 ; 2461.13,905 2461.13,905.55 v1(2461.13,930.87)
  L05 - PWR w12: 2171.62,1064.9 2110.34,1064.9 2073.5,1028.06 2073.5,936.94 2074.5,935.94 2092.16,918.28 2139.54,870.9 2229.66,870.9 2292.95,807.6 2363.32,807.6 2388.91,833.19 2452.59,833.19 2499.74,833.19 2606.05,833.19 2661.17,888.31 2661.17,913.93 2640.48,934.62 2610.92,934.62 v1(2589.09,956.46) ; v1(2281.31,981.9) 2281.31,980.27 2286.16,975.43 2286.16,973.19 2327.33,932.01 2332.03,932.01 v1(2333.18,930.87) ; v1(2435,950) 2436.62,950 2454.61,932.01 2459.99,932.01 v1(2461.13,930.87)
VSYS_1V8: C33.2 C34.2 C38.1 C39.1 C43.1 C82.1 C83.1 C84.1 C85.2 C184.1 C185.1 C186.1 C187.1 C189.1 C207.2 C218.2 J12.3 L3.2 L18.1 Q2.1 R9.2 R10.1 R33.2 R34.2 R35.2 R36.2 R37.2 R38.2 R39.2 R40.2 R41.2 R42.2 R43.2 R44.2 R66.2 R67.2 R68.2 R69.2 R70.2 R71.2 R72.2 R73.2 R187.2 R188.2 R189.2 R193.1 U1.18 U2.J5 U2.P16 U10.B4 U10.D1 U10.E4 U16.B4 U16.D1 U16.E4 U53.1 U53.5 U55.1 U55.5 | length 11178.5
  L01 - TOP w6: v1(3131,1646) 3131,1649.25 3135.27,1653.51 3135.27,1662.39 3136.61,1663.73 Q2.1@3136.61,1666.2 ; U55.1@3682.47,379 U55.1@3689.76,379 3712,379 3728.78,362.22 3745.12,362.22 U55.5@3748.02,359.32
  L01 - TOP w8: R36.2@2904.47,764.95 R34.2@2936.8,764.95 ; v1(2938.2,734.36) 2937.5,735.06 2937.5,764.25 R34.2@2936.8,764.95 ; R33.2@2969.13,764.95 R34.2@2936.8,764.95 ; v1(3004.55,842.19) 3005.18,841.56 3005.18,802.96 C85.2@3005.8,802.34
  L01 - TOP w10: v1(1491.66,1150.78) 1491.66,1154.65 1508.16,1171.16 U53.1@1535.02,1171.16 1535.26,1171.39 1535.26,1198.95 1560.37,1224.07 1560.37,1251.63 U53.5@1560.61,1251.87 ; v1(1592,1743.03) 1594.13,1745.16 1657.84,1745.16 R187.2@1658,1745.31 ; v1(2947,1503) 2947.31,1502.69 2947.31,1488.46 U1.18@2947.39,1488.38 ; v1(3634,417) 3634.34,416.66 3660.67,416.66 C218.2@3661.02,416.32 3662.98,416.32 3667.83,411.47 3667.83,393.65 U55.1@3682.47,379
  L01 - TOP w20: v1(2797,1541) 2797.74,1541 2891.74,1635 3120,1635 ; v1(3131,1646) 3120,1635 ; v1(3306,961) 3307,961 3357,1011 3357,1635 ; J12.3@4732,2956 4491.88,2715.88 4491.88,2140.88 4167,1816 3959,1816 3778,1635 3357,1635 ; 3120,1635 3357,1635
  L03 - SIG w20: v1(2797,1519) 2931,1519 v1(2947,1503)
  L05 - PWR w6: v1(2563.5,1033.23) 2589.36,1033.23 2611.23,1055.1 2636.55,1055.1 2661.17,1079.72
  L05 - PWR w10: v1(2510.6,1445.17) 2539.3,1473.87 2539.3,1490.98 v1(2568,1519.68)
  L05 - PWR w12: 2661.17,1079.72 2680.1,1098.65 2680.1,1172.65 2719.34,1211.9 2728.9,1211.9 2765.39,1248.39
  L05 - PWR w20: v1(1491.66,1150.78) 1491.66,1156.82 1398,1250.48 1398,1731.32 1409.72,1743.03 1553,1743.03 ; v1(1592,1743.03) 1553,1743.03 ; v1(1755,2138) 1763,2130 1763,2057 v1(1737.74,2031.74) 1720.32,2014.32 1699.66,2014.32 ; v1(2568,1519.68) 2568,1542.04 2621.96,1596 v1(2625.31,1596) ; v1(2797,965) 2894.35,965 v1(2936,1006.65) 2936.34,1006.32 v1(3054,1006.32) 3054,973.95 3058.9,969.05 3058.9,931.92 v1(3014.93,887.95) 3004.55,877.57 v1(3004.55,842.19) ; v1(2872,1117.65) 2872,1141.79 2765.39,1248.39 2690.1,1323.69 2690.1,1484.31 2704.89,1499.1 2745.1,1499.1 v1(2765,1519) ; v1(2938.2,734.36) 2938.2,755.1 3004.55,821.45 v1(3004.55,842.19) ; v1(3331,985) 3323,977 ; v1(3634,417) 3323,728 3323,977 ; 1553,1743.03 1553,1965.11 v1(1619.63,2031.74) 1661.57,2031.74 v1(1679,2014.32) 1699.66,2014.32 ; 1699.66,2014.32 1699.66,1914.92 v1(1698.37,1913.63) 1758.37,1913.63 v1(1824,1848) 1873.64,1848 1999.64,1722 2499.31,1722 v1(2625.31,1596) ; v1(2625.31,1596) 2710,1596 v1(2765,1541) ; v1(2765,1519) 2775,1519 ; v1(2765,1519) v1(2765,1541) ; v1(2765,1541) v1(2797,1541) ; 2775,1519 v1(2797,1541) ; 2775,1519 v1(2797,1519) v1(2797,1541) ; v1(3004.55,842.19) 3008.74,838 v1(3159,838) 3199.21,838 3252.61,891.39 3252.61,907.61 v1(3306,961) 3307,961 3323,977
  L06 - SIG w6: v1(2282,1161.18) 2305.19,1184.37 2305.19,1209.69 2325.77,1230.26 2347.56,1230.26 2366.46,1249.16 2366.46,1342.78 2468.85,1445.17 v1(2510.6,1445.17)
  L08 - BOTTOM w5: C39.1@2199.3,1154.68 2220.71,1154.68 2223.79,1151.6 2268.9,1151.6 2278.48,1161.18 v1(2282,1161.18) ; C38.1@2558.68,1060 2558.68,1041.56 2563.5,1036.75 v1(2563.5,1033.23)
  L08 - BOTTOM w6: v1(3159,838) 3160.04,839.04 3160.04,884.59 R44.2@3161.09,885.64 R38.2@3161.09,914.89 R43.2@3161.09,944.14 R42.2@3161.09,973.39 R37.2@3161.09,1002.64 R37.2@3160.61,1003.11
  L08 - BOTTOM w8: R41.2@2796.02,1057 2796.51,1056.51 2796.51,965.49 v1(2797,965) ; v1(2872,1117.65) 2873.97,1115.69 2911.03,1115.69 2926.35,1131 R193.1@2928.32,1131
  L08 - BOTTOM w10: v1(1619.63,2031.74) 1663.54,2031.74 C187.1@1679,2016.28 ; R68.2@1672,2138.98 1672.49,2138.49 1754.51,2138.49 v1(1755,2138) ; R67.2@1685.67,1847.02 R73.2@1715,1847.02 R72.2@1770.67,1847.02 R71.2@1799,1847.02 1823.02,1847.02 v1(1824,1848) ; v1(1698.37,1913.63) 1698.37,1992.98 1679,2012.35 v1(1679,2014.32) C187.1@1679,2016.28 ; v1(1737.74,2031.74) 1694.46,2031.74 C187.1@1679,2016.28
VSYS_3V3: C17.2 C18.2 C19.2 C26.1 C27.2 C28.2 C29.2 C30.2 C31.2 C32.2 C35.1 C36.1 C37.1 C54.2 C56.1 C57.1 C59.2 C61.1 C62.2 C63.1 C86.1 C111.1 C112.1 C115.1 C116.2 C117.1 C118.1 C119.1 C120.2 C123.2 C124.1 C145.1 C146.1 C147.1 C172.2 C173.2 C174.2 C175.1 C176.2 C177.1 C178.1 C180.1 C183.1 C188.1 C192.2 C193.2 C196.1 C197.1 C208.2 C211.2 C219.1 D10.2 D11.2 D12.2 D13.2 D14.2 D15.2 D16.2 D17.2 J5.1 J9.10 J11.59 J12.1 J16.5 J18.1 L2.2 L4_SOM-ETH1.2 L4_SOM-ETH2.2 L5_SOM-ETH1.2 L5_SOM-ETH2.2 L14.1 L15.1 L17.1 R3.1 R4.2 R5.2 R7.2 R8.2 R12.2 R13.2 R15.1 R17.2 R22.1 R23_SOM-ETH1.1 R23_SOM-ETH2.1 R24_SOM-ETH1.1 R24_SOM-ETH2.1 R27_SOM-ETH1.1 R27_SOM-ETH2.1 R29_SOM-ETH1.1 R29_SOM-ETH2.1 R30_SOM-ETH1.1 R30_SOM-ETH2.1 R31_SOM-ETH1.1 R31_SOM-ETH2.1 R32_SOM-ETH1.1 R32_SOM-ETH2.1 R55.2 R84.2 R85.2 R86.2 R87.2 R89.2 R90.1 R91.1 R92.1 R94.1 R99.1 R100.1 R105.1 R107.1 R124.2 R125.2 R126.2 R127.2 R133.2 R141.1 R171.2 R172.2 R173.2 R175.2 R176.2 R177.2 R178.2 R179.2 R192.2 R194.1 R196.2 R201_SOM-ETH1.1 R201_SOM-ETH2.1 R202.1 R207_SOM-ETH1.1 R207_SOM-ETH2.1 R213.2 R214.2 R216.2 R217.2 R219.2 R220.2 R221.2 R233_SOM-ETH1.1 R233_SOM-ETH2.1 R239.2 R240.2 R241.2 R242.2 SW1.5 SW1.6 SW1.7 SW1.8 SW3.C U1.2 U2.E7 U2.E12 U2.E16 U2.G5 U2.J16 U2.M5 U2.M16 U2.T7 U2.T14 U3.8 U4.5 U5.8 U6.6 U7.15 U11.8 U19.10 U20.6 U21.9 U22.2 U22.20 U23.15 U24.8 U25.5 U26.14 U27.14 U28.14 U29.5 U30.6 U31.5 U32.2 U32.3 U34.3 U40.8 U42.1 U43.1 U47.5 U48.5 U49.14 U50.1 U51.14 U52.14 U53.6 U54.5 U55.6 | length 15297.4
  L01 - TOP w5: R7.2@2986,1141 2987.97,1141 3020.97,1174 C62.2@3025.37,1174 v1(3041.12,1174) 3055.87,1174 3056.72,1173.15 U6.6@3056.72,1172.28
  L01 - TOP w6: v1(1661.92,220.65) 1663.73,218.84 1710.31,218.84 U32.3@1710.37,218.78 ; v1(1661.92,252.65) 1663.89,252.65 1682.02,234.53 U32.2@1710.37,234.53
  L01 - TOP w8: v1(648,2388) 690,2388 SW1.8@691,2389 SW1.7@691,2439 SW1.6@691,2489 SW1.5@691,2539 ; R87.2@1031.69,444 v1(1058,444) ; v1(1191,183) 1191.27,182.73 1216.28,182.73 R171.2@1216.55,182.46 ; v1(1255.92,246.46) 1284.54,246.46 1306,225 1330,225 1336.24,218.76 U48.5@1336.24,202.28 ; v1(1257.57,278.46) 1310.33,278.46 1316.55,272.24 U20.6@1316.55,270.28 ; v1(1417,299) 1417.78,298.22 1417.78,279.24 R214.2@1418.55,278.46 ; R173.2@1457.92,182.46 1458.15,182.23 1484.8,182.23 v1(1485.03,182) ; R219.2@1473,436.98 R17.2@1496,436.98 1496.49,436.49 1520.51,436.49 v1(1521,436) ; v1(1490.72,1270.09) C208.2@1490.72,1268.12 1490.72,1266.15 1505,1251.87 U53.6@1535.02,1251.87 ; v1(1589,473.65) 1589.16,473.81 1589.16,510.61 U7.15@1589.32,510.76 ; v1(1595,189) 1595.17,188.83 1622.38,188.83 R172.2@1622.55,188.65 ; R23_SOM-ETH2.1@1724.13,757.95 R233_SOM-ETH2.1@1756.13,757.95 ; v1(1756,731) 1756.07,731.07 1756.07,757.89 R233_SOM-ETH2.1@1756.13,757.95 ; U30.6@1761.55,329.65 1761.55,328.89 1763.45,326.98 1793.33,326.98 C172.2@1796,324.31 1796.66,323.66 1818.34,323.66 v1(1819,323) ; R32_SOM-ETH2.1@1821.13,757.95 R31_SOM-ETH2.1@1788.13,757.95 R233_SOM-ETH2.1@1756.13,757.95 ; L4_SOM-ETH2.2@1940.69,807.64 1941.33,807 v1(1970,807) ; R207_SOM-ETH2.1@1948.1,919.64 1948.42,919.32 1974.68,919.32 v1(1975,919) ; R27_SOM-ETH2.1@1948.82,958.64 v1(1950.79,958.64) ; U11.8@1978.5,1891.42 1978.5,1903.28 1979.22,1903.99 1995.28,1903.99 2016,1924.72 v1(2016,1928.65) 2015.66,1929 2015.66,1970.97 R55.2@2015.32,1971.31 ; v1(2016.71,676.86) 2017.51,676.86 2026.04,668.33 U47.5@2026.04,638.13 ; R217.2@2402.52,729.6 2403.89,730.98 R217.2@2404,730.98 R13.2@2431,730.98 ; v1(2510.37,1617.91) 2510.37,1587.13 L17.1@2511.58,1585.91 ; v1(2523,3049) U34.3@2523,3073.56 ; U52.14@2592.87,410.24 2592.94,410.31 2592.94,444.62 C197.1@2597.32,449 2597.16,449.16 2597.16,478.84 v1(2597,479) ; U49.14@2796.87,411.24 2796.87,441.16 2802.72,447 C196.1@2803.32,447 2802.66,447.66 2802.66,482.34 v1(2802,483) ; v1(2947,1343) 2947.2,1343.2 2947.2,1358.26 U1.2@2947.39,1358.46 ; U19.10@3064.43,483 3065.56,481.88 3094.88,481.88 3095.5,481.26 3095.5,506.5 v1(3096,507) ; v1(3083,3185) 3083,3187.71 3090.87,3195.58 3090.87,3206.19 3098.68,3214 R141.1@3102.62,3214 ; R179.2@3157,574.69 3157.66,575.34 3270.66,575.34 v1(3307,539) 3307,540 3341.69,574.69 R177.2@3375,574.69 3376.69,576.38 R175.2@3461,576.38 ; v1(3277,297) 3277.66,297.66 3304.34,297.66 C180.1@3305,298.31 3305.04,298.36 U50.1@3350.64,298.4 U50.1@3350.64,298.4 ; R175.2@3461,574.69 3510.61,574.69 3512.31,576.38 R221.2@3514,574.69 ; U54.5@3909.4,537.62 3909.54,537.47 3909.54,501.14 C211.2@3909.69,501 3914.67,505.98 3924.98,505.98 v1(3937,518) ; v1(3940,3491) 3940,3569.84 J16.5@3940.43,3570.28 ; U28.14@4040.87,505.24 4040.94,505.31 4040.94,535.62 v1(4044.31,539) ; R220.2@4167.69,465 v1(4194,465) ; U26.14@4283.87,640.24 4283.87,668.53 4290.35,675 v1(4292.31,675) ; U27.14@4462.87,640.24 4462.94,640.31 4462.94,679.62 v1(4465.31,682)
  L01 - TOP w10: v1(390,2905) D10.2@428.44,2904.99 D11.2@428.44,2855.57 D12.2@428.44,2806.16 D13.2@428.44,2756.74 D14.2@428.44,2707.32 D15.2@428.44,2657.9 D16.2@428.44,2608.48 D17.2@428.44,2559.06 428,2558.62 v1(428,2520) ; L5_SOM-ETH2.2@1508.26,1032.21 v1(1508.26,1062.65) ; L5_SOM-ETH1.2@1509.26,1475.21 v1(1509.26,1505.65) ; R24_SOM-ETH2.1@1647.13,1140.13 1647.39,1140.39 1738.13,1140.39 1739.28,1141.53 1763.47,1141.53 v1(1765,1140) ; R24_SOM-ETH1.1@1648.13,1583.13 1648.39,1583.39 1777.88,1583.39 v1(1778.13,1583.64) ; R23_SOM-ETH1.1@1733.13,1195.95 1822.13,1195.95 1826.66,1200.48 1846.52,1200.48 v1(1847,1200) ; v1(1885.66,691.52) 1885.66,654.61 1885.74,654.53 U3.8@1889.18,654.53 ; L4_SOM-ETH1.2@1941.69,1250.64 v1(1961.38,1250.64) ; R207_SOM-ETH1.1@1949.1,1362.64 1949.82,1363.35 v1@1949.82,1389.83 ; R27_SOM-ETH1.1@1949.82,1395.96 R27_SOM-ETH1.1@1949.82,1401.64 ; v1(1951.79,1389.83) 1951.79,1395.96 R27_SOM-ETH1.1@1957.46,1401.64 ; U55.6@3748.02,379 3755.31,379 3770.26,393.95 3770.26,411.47 3775.1,416.32 C219.1@3777.07,416.32 3777.41,416.66 3803.66,416.66 v1(3804,417)
  L01 - TOP w12: R85.2@1030.69,845 v1(1060,845) ; R86.2@1030.69,1685 1031.19,1685.5 1054.5,1685.5 v1(1055,1686) ; R84.2@1030.69,2085 v1(1055,2085)
  L01 - TOP w15: v1(2930,1587) 2930.35,1586.65 2986.78,1586.65 R196.2@2987.13,1586.29
  L01 - TOP w20: R194.1@2905.13,1269.27 2905.13,1269.16 2905.29,1269 v1(2930,1269) ; v1(2970,2794) 2992,2794 v1(3078,2880)
  L03 - SIG w6: v1(2282,930.87) 2330.9,979.77
  L03 - SIG w8: v1(2282,1033.23) 2282,1032.09 2305.2,1008.89 2306.74,1008.89 2325.96,989.67 2325.96,987.94 2338.32,975.58 2391.97,975.58 2403.26,964.29 ; v1(2282,1110) 2282,1111.14 2304.37,1133.5 2307.23,1133.5 2326.9,1153.17 2326.9,1169 ; v1(2333.18,1212.36) 2333.18,1209.66 2326.9,1203.38 2326.9,1169 ; v1(2384.36,930.87) 2385.5,930.87 2403.26,948.63 2403.26,964.29 ; v1(2510.54,1213.48) 2486.2,1189.13 ; v1(2563.5,1110) 2563.5,1108.86 2541.25,1086.62 ; 2326.9,1169 2466.07,1169 2486.2,1189.13 ; 2403.26,964.29 2414.33,975.36 2468.96,975.36 2488.68,955.64 ; 2486.2,1189.13 2486.2,1186.16 2504.49,1167.87 2505.85,1167.87 2518.53,1155.19 2518.53,1102.65 2530.08,1091.1 2536.77,1091.1 2541.25,1086.62 ; 2488.68,955.64 2488.68,959.06 2504.66,975.03 2507.43,975.03 2519.05,986.65 2519.05,1024.71 ; 2488.68,955.64 2488.68,953.21 2511.03,930.87 v1(2512.31,930.87) 2540.59,930.87 2563.5,953.77 v1(2563.5,982.05) 2563.5,983.19 2541.37,1005.32 2538.44,1005.32 2519.05,1024.71 ; 2519.05,1024.71 2519.01,1024.75 2519.01,1064.37 2541.25,1086.62
  L03 - SIG w10: v1(2282,1033.23) v1(2282,1110) ; v1(2510.37,1617.91) 2571.4,1617.91 v1(2625.31,1564) 2606.18,1544.86 2606.18,1527.12 v1(2604.65,1525.59)
  L03 - SIG w15: v1(2604.65,1525.59) 2683.66,1446.57 2714.43,1446.57 v1(2715,1446)
  L03 - SIG w20: v1(2795,1329) 2933,1329 v1(2947,1343) 2947,1286 v1(2930,1269)
  L05 - PWR w6: v1(2282,930.87) 2307.31,930.87 2325.21,912.97 2341.15,912.97 2354.28,926.1 2365.41,926.1 2367.88,928.57 2382.07,928.57 v1(2384.36,930.87)
  L05 - PWR w8: v1(2789.31,2937) 2806.14,2920.18 2812.48,2920.18 v1(2830.65,2902)
  L05 - PWR w10: v1(2512.31,930.87) 2542.01,930.87 2563.5,952.35 v1(2563.5,982.05)
  L05 - PWR w15: v1(2715,1446) 2715.81,1446 2721.41,1451.6 2724.28,1451.6 2747.68,1475 2818,1475 v1(2930,1587) ; v1(3041.12,1174) 3066.2,1199.09 3151.1,1199.09 3169.19,1181 v1(3170,1181)
  L05 - PWR w20: v1(74,2397) 74,2495 v1(177,2598) 304,2598 v1(347,2641) ; v1(153,2916) 153,2799.81 151,2797.81 v1(151,2797) 205.25,2797 223.25,2779 277.5,2779 ; v1(390,2905) 277.5,2792.5 277.5,2779 ; v1(748,2794) 887.7,2794 ; v1(887,2951) 887,2794.7 887.7,2794 ; v1(2952.69,3029) 3076,3029 3078,3027 ; v1(3078,2880) 3078,3027 ; 3246.32,3368.11 3201,3322.8 3201,3196.72 3189.28,3185 v1(3083,3185) 3083,3032 3078,3027 ; v1(3579,2056) 3624,2056 v1(3625,2057) 3657.31,2024.68 v1(4100,2024.68) 4136.69,1988 4401,1988 ; v1@3940,3488.33 v1(3940,3491) ; J12.1@4532,2956 4532,2119 4401,1988 ; v1(4702,1710) 4424,1988 4401,1988 ; 277.5,2779 277.5,2702.14 336.64,2643 345,2643 v1(347,2641) ; v1(347,2641) 347,2601 v1(428,2520) 595,2520 v1(624,2549) 624,2412 v1(648,2388) 824.35,2388 v1(844,2407.65) 858.65,2393 938,2393 v1(1036,2491) 1042,2497 1042,2715.32 1033,2724.32 v1(1033,2792) 1031,2794 887.7,2794
  L06 - SIG w8: v1(2282,1033.23) 2282,1032.09 2305.2,1008.89 2306.74,1008.89 2325.96,989.67 2325.96,987.94 2338.54,975.36 2392.19,975.36 2410.74,956.8 2410.74,956.11 ; v1(2384.36,930.87) 2385.5,930.87 2410.74,956.11 ; v1(2512.31,930.87) 2511.03,930.87 2488.68,953.21 2488.68,955.64 ; v1(2563.5,982.05) 2563.5,983.19 2541.04,1005.64 2538.76,1005.64 ; v1(2563.5,1110) 2563.5,1108.86 2519.01,1064.37 2519.01,1025.4 2538.76,1005.64 ; 2410.74,956.11 2429.99,975.36 2468.96,975.36 2488.68,955.64 ; 2488.68,955.64 2488.68,959.06 2504.66,975.03 2507.43,975.03 2519.05,986.65 2519.05,989.92 2534.77,1005.64 2538.76,1005.64
  L06 - SIG w12: v1(2282,1033.23) v1(2282,1110)
  L08 - BOTTOM w5: C36.1@2451.68,1181 2453.65,1181 2467.62,1194.96 2468.34,1194.96 2470.99,1197.61 2497.56,1197.61 C28.2@2512.31,1212.36
  L08 - BOTTOM w6: v1(347,2641) 347.73,2641.73 392.06,2641.73 U22.2@392.8,2642.47 ; v1(2510.54,1213.48) 2510.54,1235.9 2536.2,1261.56 ; C37.1@2514.32,1292 2516.28,1292 2536.2,1272.08 2536.2,1262.59
  L08 - BOTTOM w8: v1(74,2397) 74,2429.17 90.97,2446.14 90.97,2463.69 R12.2@96.81,2469.54 ; R213.2@112.31,2721.22 114.28,2721.22 143.87,2750.81 143.87,2763.09 150.06,2769.28 151.34,2769.28 151.34,2796.66 v1(151,2797) ; U25.5@116.69,2609.13 145.52,2609.13 155.16,2599.5 155.16,2597.84 176.84,2597.84 v1(177,2598) ; R92.1@151.68,2834 R94.1@151.68,2873.37 152.34,2874.03 152.34,2915.34 v1(153,2916) 152.34,2916.66 152.34,2989.34 R91.1@151.68,2990 ; v1(648,2388) 648.63,2388.63 648.63,2409 678.82,2439.19 678.82,2441.16 684.66,2447 R107.1@686.63,2447 ; U23.15@837.28,2447.04 838,2446.32 838,2435.5 844,2429.5 v1(844,2407.65) C177.1@844,2405.68 ; v1(887,2951) 887.35,2950.65 887.35,2870.95 U24.8@887.7,2870.6 ; R105.1@989.68,2492 990.18,2491.5 1035.5,2491.5 v1(1036,2491) ; U31.5@1535.84,375.75 1535.84,374.62 1537.75,372.72 1574.28,372.72 1576.16,370.84 1598.84,370.84 v1(1600,372) ; U5.8@1554.32,1121.68 1554.32,1082.84 1560.16,1077 v1(1561.32,1077) ; R127.2@2038.46,86 2038.96,86.5 2067.28,86.5 v1(2067.78,87) ; R126.2@2038.46,135.67 2038.96,136.17 2067.28,136.17 v1(2067.78,136.67) ; R125.2@2038.46,185.33 2038.96,185.83 2067.28,185.83 v1(2067.78,186.33) ; R124.2@2038.46,235 2038.96,235.5 2067.28,235.5 v1(2067.78,236) ; U21.9@2432.5,463 2432.56,463.06 2447.75,463.06 2473.19,488.5 2475.16,488.5 2481,494.35 v1(2481,496.32) ; v1(2456,2812) v1(2456,3065.69) 2506.31,3065.69 v1(2523,3049) ; L14.1@2587,1371 2586.5,1371.5 2586.5,1433.5 v1(2586,1434) C54.2@2595.99,1434 ; v1(2632,2781) 2632,2781.65 2787.35,2937 v1(2789.31,2937) ; L15.1@2697.68,1371 C57.1@2697.68,1403 2695.72,1403 2689.8,1408.92 C59.2@2689.8,1435.36 2690.97,1436.54 2692.77,1436.54 2702.04,1445.8 2714.8,1445.8 v1(2715,1446) ; v1(2830.65,2902) 2838.78,2910.13 U51.14@2871.76,2910.13 ; R242.2@2968.69,2820 2969.34,2819.34 2969.34,2794.66 v1(2970,2794) ; v1(3078,2880) R241.2@3078,2907 R240.2@3078,2939 ; R4.2@3087,1762.31 3087.66,1761.66 3241.84,1761.66 v1(3242.5,1761) ; U43.1@4055,2016.91 4062.78,2024.68 v1(4100,2024.68) ; v1(4702,1710) 4702,1688.41 4703.49,1686.91 J11.59@4737.2,1686.91
  L08 - BOTTOM w10: v1(624,2549) 624.34,2549.34 624.34,2575.66 C112.1@624.68,2576 624.68,2616.48 U22.20@625.08,2616.88 ; v1(2282,1110) 2282,1107.45 2290.5,1098.94 2290.5,1084.84 2295.35,1080 C35.1@2297.32,1080 ; v1(2954.68,1172) 2991.13,1172 3000.72,1181.59 U29.5@3005.65,1181.59 ; R8.2@3126,1137.31 3159.14,1137.31 3170,1148.17 v1(3170,1181) ; U42.1@3536,2019.91 3573.19,2019.91 3579,2025.72 C146.1@3579,2027.68 v1(3579,2056) ; v1(3625,2057) 3624.5,2056.5 3624.5,2026.18 C145.1@3624,2025.68 3624,2023.72 3630.22,2017.5 U40.8@3669,2017.5
  other v1: 1839,223.65 1643,433.32 1459,510 2404,729.6 2764,1309 2795,1309 2764,1329 2409.05,1606.91
VSYS_MON_AM261: C52.2 R1.1 R2.2 U2.Y4 | length 124.4
  L08 - BOTTOM w8: C52.2@2494.15,1367.46 2494.15,1365.66 2501.01,1358.8 R2.2@2524.15,1358.8 R1.1@2556.15,1358.8 2556.15,1356.83 2587.17,1325.8 2587.17,1316.64 v1(2589.09,1314.72)
VSYS_USB_5V: C100.1 C101.1 C131.2 C133.1 Q4.4 Q4.7 R63.2 U15.3 U15.6 U37.7 U37.8 | length 878
  L01 - TOP w10: v1(974,3091) 976.16,3091 986.3,3101.13 U15.3@1042.28,3101.13 ; U15.6@1117.09,2992.87 1117.04,2992.91 v1(1117,3025) v1(1117,3025) 1117.12,3024.88 1169.56,3024.88 C100.1@1169.68,3024.76 v1(1169.68,3042.5) C101.1@1169.68,3060.24 ; v1(2061,3122) 2070.94,3122 2072.39,3123.44 2080.49,3123.44 C131.2@2093.33,3136.28 ; v1(2061,3146) 2083.61,3146 C131.2@2091,3138.61 ; U37.7@2076.4,3074.13 2081.17,3074.13 2089.2,3082.16 ; U37.8@2076.4,3093.81 2081.17,3093.81 2081.24,3093.73 2081.24,3092.86 2087.1,3087 C133.1@2105.5,3087 ; v1(2091,3166) C131.2@2091,3138.61 ; C133.1@2112.32,3087 2111.97,3087 2107.12,3091.84 2107.12,3123.44 2094.28,3136.28 C131.2@2093.33,3136.28 ; C131.2@2091,3138.61 C131.2@2093.33,3136.28
  L01 - TOP w15: Q4.7@954.39,3089.74 955.07,3090.43 973.43,3090.43 v1(974,3091) ; Q4.4@954.39,3124.39 954.69,3124.69 972.69,3124.69 v1(973,3125)
  L05 - PWR w10: v1(973,3125) 973,3309.16 1022,3358.16 v1(1022,3542.31)
VUSB_5V: C126.2 C128.1 C130.2 C132.1 C137.1 L9.2 R135.2 R136.2 R137.2 R138.2 U33.12 U37.1 U37.2 U37.4 U39.5 | length 1464.9
  L01 - TOP w5: U33.12@2336.53,3046.62 2381.94,3046.62 v1(2382.31,3047)
  L01 - TOP w8: U39.5@2317.69,2896.87 2318.71,2895.84 2356.29,2895.84 v1(2357.31,2894.81)
  L01 - TOP w10: 1968.32,3180.54 1915.54,3180.54 1894,3159 1894,3032 1919,3007 v1(2003,3007) 2003,3034.68 2002.92,3034.76 U37.4@2001.6,3034.76 ; C130.2@1992.67,3137.28 1991.72,3137.28 1978.88,3124.44 1978.88,3105.91 1978.53,3105.56 1978.53,3096.82 C132.1@1972.83,3091.13 ; U37.2@2001.6,3074.13 1996.83,3074.13 1989.52,3081.44 1970.86,3081.44 C132.1@1966.02,3086.28 1967.99,3086.28 C132.1@1972.83,3091.13 ; U37.1@2001.6,3093.81 1975.51,3093.81 C132.1@1972.83,3091.13
  L01 - TOP w20: C130.2@1991.72,3137.28 1983.88,3145.12 1983.88,3164.98 1968.32,3180.54 C126.2@1968.32,3229.33 1971.74,3225.9 2022.89,3225.9 L9.2@2026.32,3222.47
  L08 - BOTTOM w10: v1(2003,3007) 2084.72,3007 2137.4,2954.31 v1(2240,2954.31) v1(2240,3078.65) 2241.53,3080.18 2260.9,3080.18 2262.72,3082 2347.31,3082 v1(2382.31,3047) 2382.31,2976.41 2398.65,2960.07 v1(2398.65,2958.81) v1(2398.65,2926.81) 2368.18,2896.34 2358.85,2896.34 v1(2357.31,2894.81)
XDS_EMU0: R151.2 U41.42 | length 86.3
  L08 - BOTTOM w4.5: 3805.69,2479.31 3812,2473 R151.2@3812,2454.69
  L08 - BOTTOM w6: U41.42@3800.37,2536.15 3800.37,2484.63 3805.69,2479.31
XDS_EMU1: R152.2 U41.43 | length 84.8
  L08 - BOTTOM w6: R152.2@3779,2455.69 R152.2@3780,2454.69 3780,2491.38 3784.62,2496 U41.43@3784.62,2536.15
XDS_VBUS_DETECT: C140.1 R147.1 R148.2 U41.1 | length 165
  L08 - BOTTOM w6: U41.1@4001.16,3083.39 4001.16,3179.16 C140.1@4002,3180 R148.2@4036,3180 R147.1@4070,3180
XDSET_1_D_N: J15.2 U41.93 U44.5 U44.6 | length 1454.5
  L01 - TOP w4.5: v1(3449,3030) 3459,3040 4039.3,3040 4351,3351.7 4552.73,3351.7 4579.18,3378.15 4579.18,3386 4584.37,3391.19 U44.5@4584.37,3404.56 U44.6@4584.37,3437.44 4583.98,3437.83 4583.98,3498.68 J15.2@4583.59,3499.07
  L08 - BOTTOM w4.5: U41.93@3394.86,3036.15 3439.2,3036.15 3445.35,3030 v1(3449,3030)
XDSET_1_D_P: J15.3 U41.94 U44.4 U44.7 | length 1438.5
  L01 - TOP w4.5: v1(3449,3055) 3454.7,3049.3 4035.45,3049.3 4347.15,3361 4548.88,3361 4569.88,3382 4569.88,3386 4564.69,3391.19 U44.4@4564.69,3404.56 U44.7@4564.69,3437.44 4564.69,3456.4 4558,3463.09 J15.3@4558,3499.07
  L08 - BOTTOM w4.5: U41.94@3394.86,3051.9 3430.9,3051.9 3431,3052 3435,3052 3435.42,3052.42 3446.42,3052.42 v1(3449,3055)
XDSET_1_ID: J15.4 R145.2 U44.2 U44.9 | length 1565.7
  L01 - TOP w4.3: v1(3233,3063) 3429.92,3063 3441.07,3074.15 3836.85,3074.15 3837,3074 4017.3,3074 4318.7,3375.4 4503.34,3375.4 4525.31,3397.38 U44.2@4525.31,3404.56
  L01 - TOP w6: U44.2@4525.31,3404.56 U44.9@4525.31,3437.44 4525.31,3454.31 4532.41,3461.41 J15.4@4532.41,3499.07
  L08 - BOTTOM w4.3: v1(3233,3063) 3262.63,3063 R145.2@3262.98,3063.35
